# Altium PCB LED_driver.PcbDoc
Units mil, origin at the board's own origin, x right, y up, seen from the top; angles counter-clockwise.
Board outline 6000 x 4000 mil, 2 copper layers (Top Layer, Bottom Layer); 9 components, 7 nets, 22 pads, 3 vias.
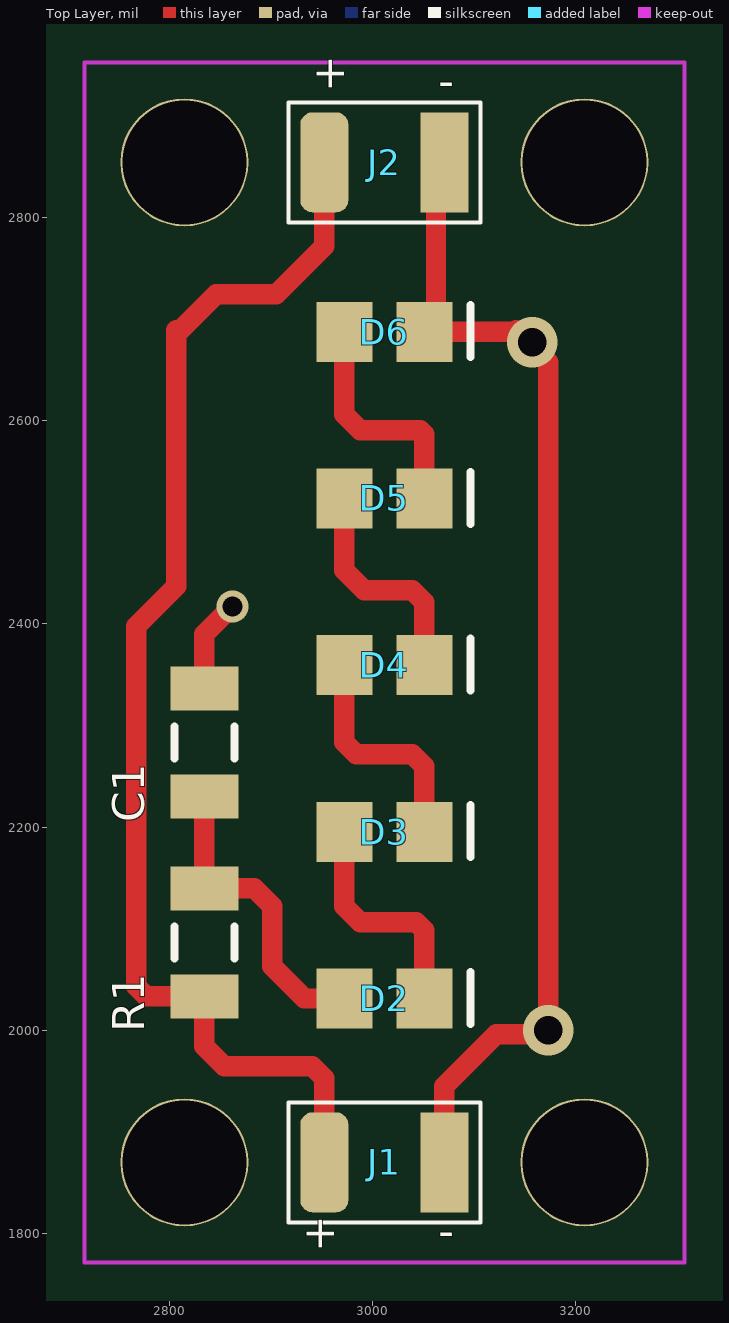
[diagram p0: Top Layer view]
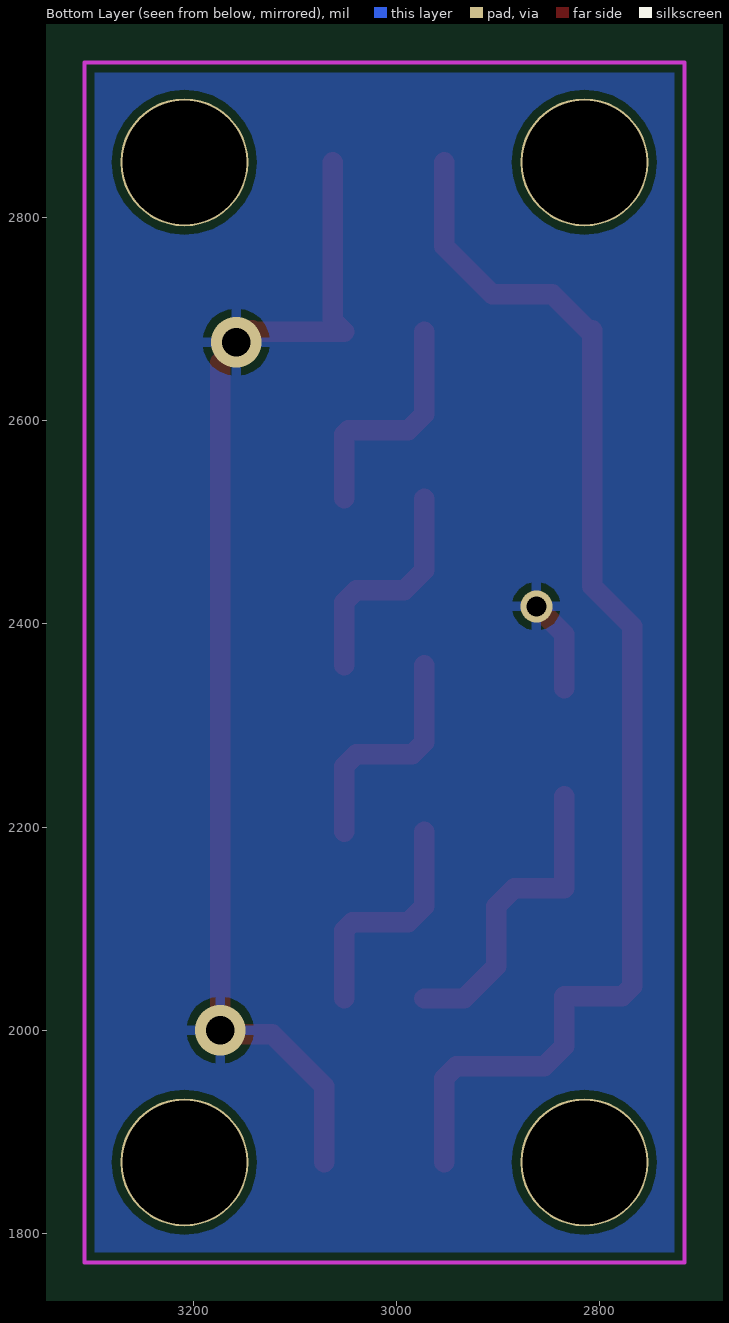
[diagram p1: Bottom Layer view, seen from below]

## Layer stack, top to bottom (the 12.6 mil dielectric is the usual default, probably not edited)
Top Layer: signal copper 1.4
Dielectric: dielectric 12.6, FR-4, Dk 4.8
Bottom Layer: signal copper 1.4

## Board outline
1000,1000 7000,1000 7000,5000 1000,5000

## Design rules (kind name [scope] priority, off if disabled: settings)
Clearance Clearance_1 [All] p1 off: gap=15.75
Clearance [All] p2: gap=7.87
PolygonConnect [All] p1: connectstyle=Relief reliefconductorwidth=10 reliefentries=4 polygonreliefangle="90 Angle"
RoutingVias [All] p1: holewidth=28 width=50 viastyle="Through Hole" minholewidth=28 minwidth=50 maxholewidth=28 maxwidth=50
SilkscreenOverComponentPads [All] p1: minsilkscreentomaskgap=10
SolderMaskExpansion [All] p1: expansion=4
Width [All] p1: maxlimit=39.37 minlimit=7.87 preferedwidth=19.68 minimp=50.000000 maximp=50.000000 favimp=50.000000
27 further rules are at their usual default settings.

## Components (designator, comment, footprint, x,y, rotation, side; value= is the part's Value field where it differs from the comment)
C1 "Cap Semi" C1206 2834.65,2283.46 r270 top
D2 "LED2" LED_0805 3011.81,2031.36 r0 top
D3 "LED2" LED_0805 3011.81,2195.41 r0 top
D4 "LED2" LED_0805 3011.81,2359.45 r0 top
D5 "LED2" LED_0805 3011.81,2523.49 r0 top
D6 "LED2" LED_0805 3011.81,2687.53 r0 top
J1 "Header 2H" CON2_S 3011.81,1870.08 r0 top
J2 "Header 2H" CON2_S 3011.81,2854.33 r0 top
R1 "Res3" C1206 2834.65,2086.61 r270 top

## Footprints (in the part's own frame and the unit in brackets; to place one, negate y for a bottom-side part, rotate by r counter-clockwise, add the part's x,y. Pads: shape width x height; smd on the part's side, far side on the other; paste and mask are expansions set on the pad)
C1206 [mm] "Chip Capacitor, Body 3.2x1.6mm, IPC High Density"
  rect 1.1x1.7 smd: 1(-1.35,0) 2(1.35,0)
  silkscreen extent -0.4,-0.75 0.4,0.75, body extent -1.7,-0.9 1.7,0.9, height 1.3
CON2_S [mm] "Connector , surface mount, wire to board"
  rrect50% 1.2x2.5 smd: 1(-1.5,0)
  rect 1.2x2.5 smd: 2(1.5,0)
  silkscreen extent -2.4,-1.5 2.4,1.5
LED_0805 [mm]
  rect 1.4x1.5 smd: 1(-1,0) 2(1,0)
  silkscreen extent 2.16,-0.64 2.16,0.67, body extent -1.07,-0.7 1.07,0.7, height 0.7

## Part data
C1: "Capacitor (Semiconductor SIM Model)"
D2 D3 D4 D5 D6: "Typical RED, GREEN, YELLOW, AMBER GaAs LED"
J1 J2: "Header, 2-Pin, Right Angle"
R1: "Resistor"

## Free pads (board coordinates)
  round 125.98 hole 122.05: 3(2814.96,1870.08) 3(2814.96,2854.33) 3(3208.66,1870.08) 3(3208.66,2854.33)

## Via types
v1: diameter 50, hole 28, Top Layer to Bottom Layer, 2 vias
v2: diameter 31.5, hole 19.68, Top Layer to Bottom Layer, 1 vias

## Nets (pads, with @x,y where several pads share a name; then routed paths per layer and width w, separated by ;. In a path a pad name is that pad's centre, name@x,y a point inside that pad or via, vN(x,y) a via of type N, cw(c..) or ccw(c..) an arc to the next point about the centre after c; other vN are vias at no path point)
+12V: C1.2 D2.1 R1.1 | length 307.9
  Top Layer w20: C1.2 R1.1 2883.86,2139.76 2901.57,2122.05 2901.57,2062.86 2933.07,2031.36 D2.1
GND: C1.1 D6.2 J1.2 J2.2 | length 1232.2
  Top Layer w20: C1.1 2834.65,2389.76 v2@2854.33,2409.45 ; J2.2@3062.6,2854.33 3062.6,2698.95 D6.2 3140.29,2687.53 3141.73,2688.98 v1@3153.54,2677.17 ; J1.2 3070.87,1944.88 3122.05,1996.06 v1@3157.48,1996.06 ; v1(3157.48,2677.17) v1@3153.54,2677.17 ; v1(3173.23,2000) 3173.23,2657.48 v1@3153.54,2677.17
  other v2: 2862.2,2417.32
NetD2_2: D2.2 D3.1 | length 228.9
  Top Layer w20: D3.1 2972.44,2122.05 2988.19,2106.3 3043.31,2106.3 3051.18,2098.43 D2.2
NetD3_2: D3.2 D4.1 | length 228.9
  Top Layer w20: D4.1 2972.44,2283.46 2984.25,2271.65 3039.37,2271.65 3051.18,2259.84 D3.2
NetD4_2: D4.2 D5.1 | length 224.3
  Top Layer w20: D5.1 2972.44,2452.76 2992.13,2433.07 3039.37,2433.07 3051.18,2421.26 D4.2
NetD5_2: D5.2 D6.1 | length 231.3
  Top Layer w20: D6.1 2972.44,2606.3 2988.19,2590.55 3047.24,2590.55 3051.18,2586.61 D5.2
NetJ1_1: J1.1 J2.1 R1.2 | length 1258.6
  Top Layer w20: J1.1 2952.76,1952.76 2940.94,1964.57 2854.33,1964.57 2834.65,1984.25 R1.2 2777.56,2033.46 2767.72,2043.31 2767.72,2397.64 2807.09,2437.01 2807.09,2688.98 2811.02,2688.98 2846.46,2724.41 2905.51,2724.41 2952.76,2771.65 J2.1

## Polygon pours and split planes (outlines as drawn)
GND on Bottom Layer "Top Layer-No Net" (solid, remove dead copper, pour order 3): 2716.54,2952.76 3307.09,2952.76 3307.09,1771.65 2716.54,1771.65

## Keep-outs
Keep-Out Layer:
  lines w3.94: 2716.54,1771.65 2716.54,2637.8 2716.54,2952.76 3307.09,2952.76 3307.09,2637.8 3307.09,1771.65 2716.54,1771.65

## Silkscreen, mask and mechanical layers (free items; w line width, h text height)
Top Overlay:
  text "-" at 3080.71,2942.91 h31.5 r180
  text "+" at 2972.44,2923.23 h31.5 r90
  text "-" at 3080.71,1811.02 h31.5 r180
  text "+" at 2962.6,1781.5 h31.5 r90
Mechanical 1:
  lines w3.94: 2627.95,2362.2 3385.83,2362.2 ; 2716.54,2637.8 2716.54,2007.87 2716.54,1850.39 2716.54,1771.65 3307.09,1771.65 3307.09,2007.87 3307.09,2637.8 ; 3011.81,1692.91 3011.81,2992.13

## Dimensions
2637.8,1870.08 to 2637.8,1771.65 on Mechanical 15
2814.96,1712.6 to 2716.54,1712.6 on Mechanical 15
2716.54,3070.87 to 3307.09,3070.87 on Keep-Out Layer
3385.83,1771.65 to 3464.57,2952.76 on Keep-Out Layer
